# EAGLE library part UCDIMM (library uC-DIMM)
Lineo's uC-DIMM module with AMP SO-DIMM Socket Standart uC-DIMM bus for all Lineo's Embedded Linux modules www.lineo.com
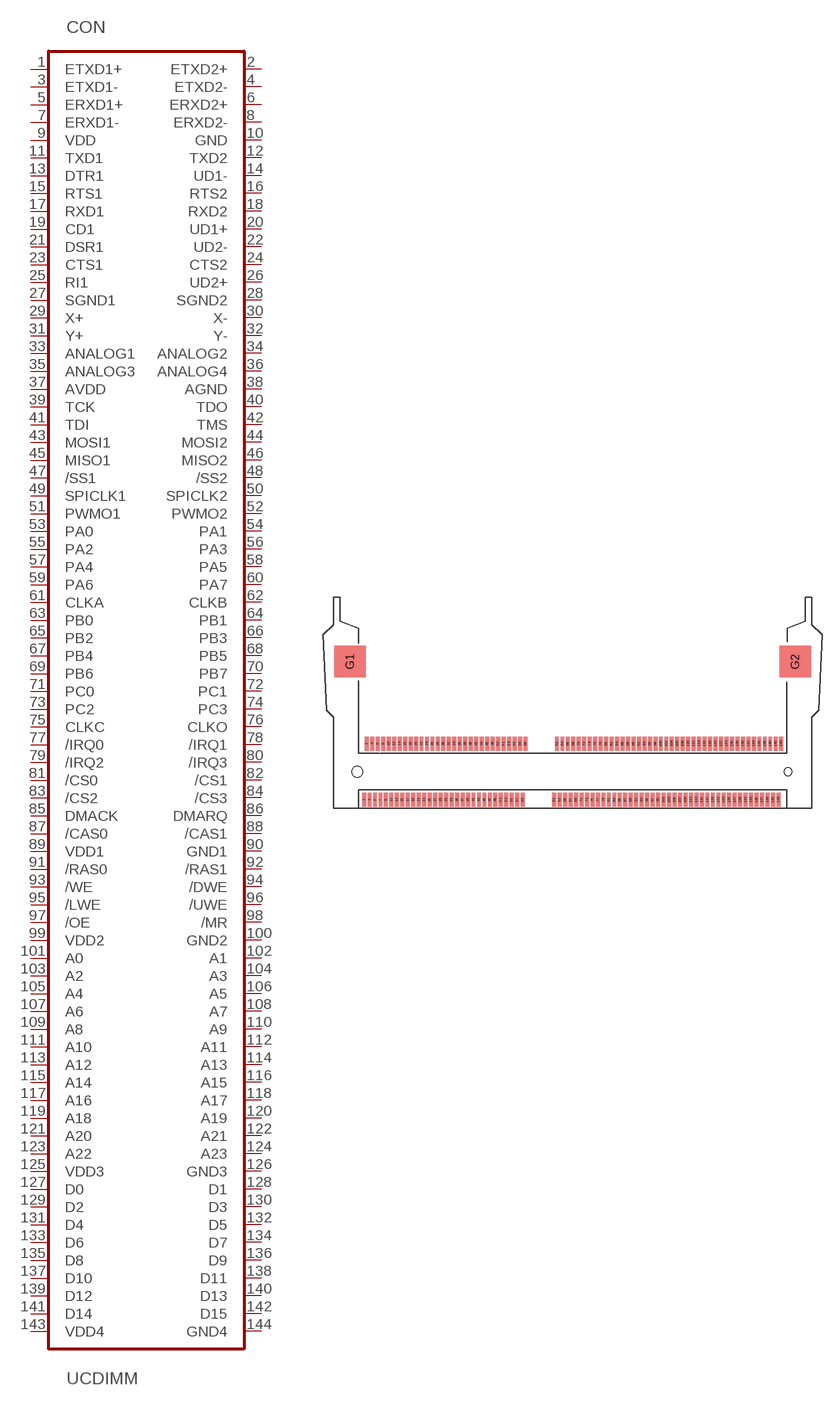
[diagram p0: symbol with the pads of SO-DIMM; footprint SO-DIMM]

Designator prefix CON

## UCDIMM-SOCKET  [SO-DIMM]
1  ETXD1+
2  ETXD2+
3  ETXD1-
4  ETXD2-
5  ERXD1+
6  ERXD2+
7  ERXD1-
8  ERXD2-
9  VDD
10  GND
11  TXD1
12  TXD2
13  DTR1
14  UD1-
15  RTS1
16  RTS2
17  RXD1
18  RXD2
19  CD1
20  UD1+
21  DSR1
22  UD2-
23  CTS1
24  CTS2
25  RI1
26  UD2+
27  SGND1
28  SGND2
29  X+
30  X-
31  Y+
32  Y-
33  ANALOG1
34  ANALOG2
35  ANALOG3
36  ANALOG4
37  AVDD
38  AGND
39  TCK
40  TDO
41  TDI
42  TMS
43  MOSI1
44  MOSI2
45  MISO1
46  MISO2
47  /SS1
48  /SS2
49  SPICLK1
50  SPICLK2
51  PWMO1
52  PWMO2
53  PA0
54  PA1
55  PA2
56  PA3
57  PA4
58  PA5
59  PA6
60  PA7
61  CLKA
62  CLKB
63  PB0
64  PB1
65  PB2
66  PB3
67  PB4
68  PB5
69  PB6
70  PB7
71  PC0
72  PC1
73  PC2
74  PC3
75  CLKC
76  CLKO
77  /IRQ0
78  /IRQ1
79  /IRQ2
80  /IRQ3
81  /CS0
82  /CS1
83  /CS2
84  /CS3
85  DMACK
86  DMARQ
87  /CAS0
88  /CAS1
89  VDD1
90  GND1
91  /RAS0
92  /RAS1
93  /WE
94  /DWE
95  /LWE
96  /UWE
97  /OE
98  /MR
99  VDD2
100  GND2
101  A0
102  A1
103  A2
104  A3
105  A4
106  A5
107  A6
108  A7
109  A8
110  A9
111  A10
112  A11
113  A12
114  A13
115  A14
116  A15
117  A16
118  A17
119  A18
120  A19
121  A20
122  A21
123  A22
124  A23
125  VDD3
126  GND3
127  D0
128  D1
129  D2
130  D3
131  D4
132  D5
133  D6
134  D7
135  D8
136  D9
137  D10
138  D11
139  D12
140  D13
141  D14
142  D15
143  VDD4
144  GND4

## Footprint SO-DIMM (pad centres in mm)
AMP 390332-1 SO-DIMM Socket
smd 0.5 x 2: 1 -26.94,-4.1; 2 -26.54,4.1; 3 -26.14,-4.1; 4 -25.74,4.1; 5 -25.34,-4.1; 6 -24.94,4.1; 7 -24.54,-4.1; 8 -24.14,4.1; 9 -23.74,-4.1; 10 -23.34,4.1; 11 -22.94,-4.1; 12 -22.54,4.1; 13 -22.14,-4.1; 14 -21.74,4.1; 15 -21.34,-4.1; 16 -20.94,4.1; 17 -20.54,-4.1; 18 -20.14,4.1; 19 -19.74,-4.1; 20 -19.34,4.1; 21 -18.94,-4.1; 22 -18.54,4.1; 23 -18.14,-4.1; 24 -17.74,4.1; 25 -17.34,-4.1; 26 -16.94,4.1; 27 -16.54,-4.1; 28 -16.14,4.1; 29 -15.74,-4.1; 30 -15.34,4.1; 31 -14.94,-4.1; 32 -14.54,4.1; 33 -14.14,-4.1; 34 -13.74,4.1; 35 -13.34,-4.1; 36 -12.94,4.1; 37 -12.54,-4.1; 38 -12.14,4.1; 39 -11.74,-4.1; 40 -11.34,4.1; 41 -10.94,-4.1; 42 -10.54,4.1; 43 -10.14,-4.1; 44 -9.74,4.1; 45 -9.34,-4.1; 46 -8.94,4.1; 47 -8.54,-4.1; 48 -8.14,4.1; 49 -7.74,-4.1; 50 -7.34,4.1; 51 -6.94,-4.1; 52 -6.54,4.1; 53 -6.14,-4.1; 54 -5.74,4.1; 55 -5.34,-4.1; 56 -4.94,4.1; 57 -4.54,-4.1; 58 -4.14,4.1; 59 -3.74,-4.1; 60 -3.34,4.1; 61 0.86,-4.1; 62 1.26,4.1; 63 1.66,-4.1; 64 2.06,4.1; 65 2.46,-4.1; 66 2.86,4.1; 67 3.26,-4.1; 68 3.66,4.1; 69 4.06,-4.1; 70 4.46,4.1; 71 4.86,-4.1; 72 5.26,4.1; 73 5.66,-4.1; 74 6.06,4.1; 75 6.46,-4.1; 76 6.86,4.1; 77 7.26,-4.1; 78 7.66,4.1; 79 8.06,-4.1; 80 8.46,4.1; 81 8.86,-4.1; 82 9.26,4.1; 83 9.66,-4.1; 84 10.06,4.1; 85 10.46,-4.1; 86 10.86,4.1; 87 11.26,-4.1; 88 11.66,4.1; 89 12.06,-4.1; 90 12.46,4.1; 91 12.86,-4.1; 92 13.26,4.1; 93 13.66,-4.1; 94 14.06,4.1; 95 14.46,-4.1; 96 14.86,4.1; 97 15.26,-4.1; 98 15.66,4.1; 99 16.06,-4.1; 100 16.46,4.1; 101 16.86,-4.1; 102 17.26,4.1; 103 17.66,-4.1; 104 18.06,4.1; 105 18.46,-4.1; 106 18.86,4.1; 107 19.26,-4.1; 108 19.66,4.1; 109 20.06,-4.1; 110 20.46,4.1; 111 20.86,-4.1; 112 21.26,4.1; 113 21.66,-4.1; 114 22.06,4.1; 115 22.46,-4.1; 116 22.86,4.1; 117 23.26,-4.1; 118 23.66,4.1; 119 24.06,-4.1; 120 24.46,4.1; 121 24.86,-4.1; 122 25.26,4.1; 123 25.66,-4.1; 124 26.06,4.1; 125 26.46,-4.1; 126 26.86,4.1; 127 27.26,-4.1; 128 27.66,4.1; 129 28.06,-4.1; 130 28.46,4.1; 131 28.86,-4.1; 132 29.26,4.1; 133 29.66,-4.1; 134 30.06,4.1; 135 30.46,-4.1; 136 30.86,4.1; 137 31.26,-4.1; 138 31.66,4.1; 139 32.06,-4.1; 140 32.46,4.1; 141 32.86,-4.1; 142 33.26,4.1; 143 33.66,-4.1; 144 34.06,4.1
smd 4.5 x 4.6: G1 -28.99,16.1; G2 36.11,16.1
hole 1.6 at -27.94,0
hole 1.1 at 35.06,0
